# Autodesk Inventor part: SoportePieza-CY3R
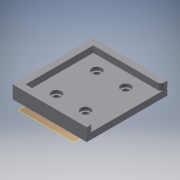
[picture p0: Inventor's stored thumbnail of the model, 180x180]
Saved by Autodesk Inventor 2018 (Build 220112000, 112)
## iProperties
Created: 2021-01
Part Number: SoportePieza-CY3R
Material: Genérico
Document SubType Name: Modeling
Designer: ATOUZA
Density: 1 g/cm^3
Appearance: Valor por defecto
Author: ATOUZA
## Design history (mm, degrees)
node "Plano de trabajo1"
sketch "Boceto1"
  geometry: L1 (5.25, -47.5)-(-36.75, -47.5); L2 (-36.75, -47.5)-(-36.75, -5.5); L3 (-36.75, -5.5)-(5.25, -5.5); L4 (5.25, -5.5)-(5.25, -47.5); L5 (5.25, -47.5)-(-36.75, -5.5); L6 (-36.75, -47.5)-(5.25, -5.5); C1 r 2 at (-26, -39); C2 r 2 at (-26, -14); C3 r 2 at (-8, -39); C4 r 2 at (-8, -14); 2 further points
  constraints: 12 end point, 4 centre point, 2 midpoint, 2 parallel, 1 horizontal, 1 perpendicular
  dimensions: "d0" = 42 distance of L2.end L3.end; "d1" = 42 distance of L1.end L2.end
extrude "Extrusión1" new body sketch "Boceto1" distance "d2" = 4; taper "d3" = 0 deg
node "Plano de trabajo2"
sketch "Boceto2"
  geometry: L1 (5.25, -47.5)-(5.25, -5.5) reference; L2 (5.25, -5.5)-(5.25, -1.5); L3 (5.25, -1.5)-(-40.75, -1.5); L4 (-40.75, -1.5)-(-40.75, -51.5); L5 (-40.75, -51.5)-(5.25, -51.5); L6 (5.25, -51.5)-(5.25, -47.5); L7 (5.25, -47.5)-(-36.75, -47.5); L8 (5.25, -5.5)-(-36.75, -5.5) reference; L9 (-36.75, -47.5)-(-36.75, -5.5); L10 (-36.75, -5.5)-(5.25, -5.5); 1 further point
  constraints: 16 end point, 7 perpendicular, 1 point on line, 1 vertical
  dimensions: "d4" = 4 distance of L1.end L2.end; "d5" = 46 distance of L2.end L3.end; "d6" = 50 distance of L3.end L4.end
extrude "Extrusión2" join sketch "Boceto2" distance "d7" = 8; taper "d8" = 0 deg
fillet "Empalme1" dims "d9" = 2
hole "Agujero1" diameter "d12" = 3; stored, may be unused: countersink angle "d16" = 90 deg, drill point angle "d18" = 118 deg; dims "d13" = 6, "d14" = 6, "d15" = 2, "d17" = 8, "d19" = 10, "d20" = 10
hole "Agujero2" diameter "d23" = 3; stored, may be unused: countersink angle "d27" = 90 deg, drill point angle "d29" = 118 deg; dims "d21" = 10, "d22" = 10, "d24" = 6, "d25" = 6, "d26" = 2, "d28" = 8
hole "Agujero3" diameter "d32" = 3; stored, may be unused: countersink angle "d36" = 90 deg, drill point angle "d38" = 118 deg; dims "d30" = 10, "d31" = 10, "d33" = 6, "d34" = 6, "d35" = 2, "d37" = 8
hole "Agujero4" diameter "d41" = 3; stored, may be unused: countersink angle "d45" = 90 deg, drill point angle "d47" = 118 deg; dims "d39" = 10, "d40" = 10, "d42" = 6, "d43" = 6, "d44" = 2, "d46" = 8
node "Sólido1"
